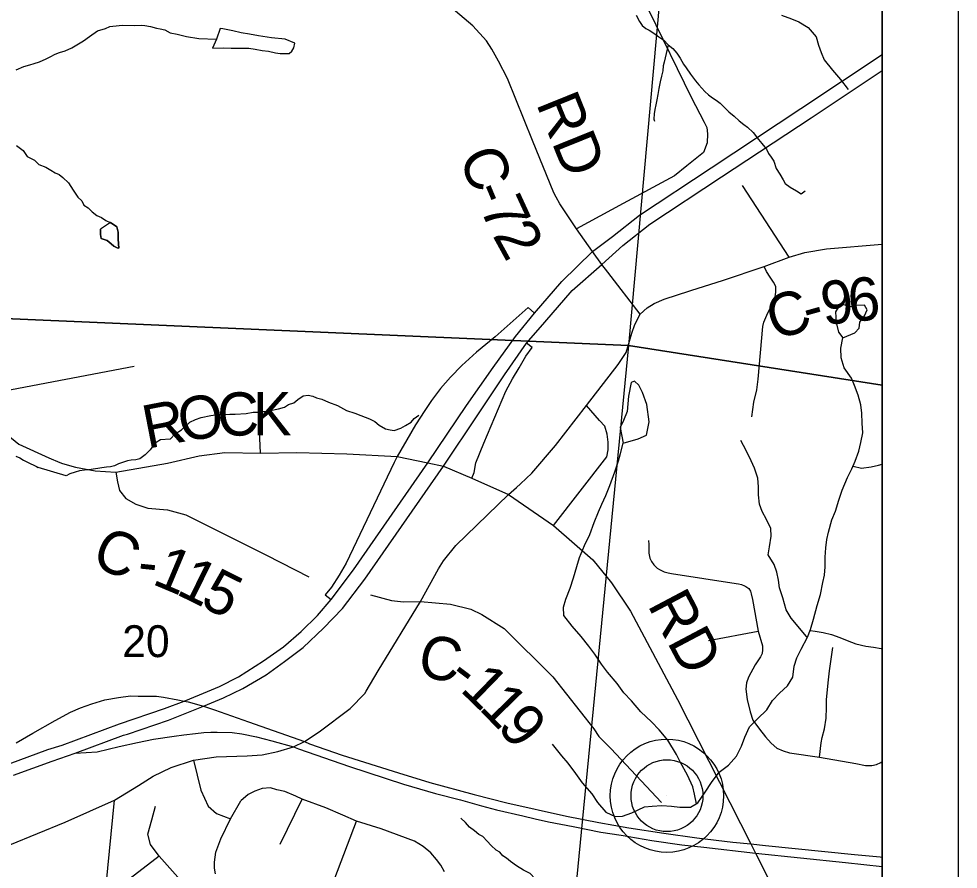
# Model space of a CAD drawing. Extents: x 0 to 34, y 0 to 22.
# Drawn here: x 7.766 to 9, y 18.274 to 19.391 of the extents above; entities that cross this region are included whole.
import ezdxf

# ---------------------------------------------------------------- set-up
doc = ezdxf.new("R2010")
doc.units = 0
for name, color, linetype in [('Default', 7, 'Continuous'), ('GM_X_County_Road', 7, 'Continuous'), ('GM_X_County_Road_Text', 7, 'Continuous'), ('GM_X_Interchange_Ramps', 7, 'Continuous'), ('GM_X_Interstate_Route', 7, 'Continuous'), ('GM_X_Minor_Lake', 7, 'Continuous'), ('GM_X_Minor_River', 7, 'Continuous'), ('GM_X_Section', 7, 'Continuous'), ('GM_X_Section_Text', 7, 'Continuous'), ('GM_X_State_Route', 7, 'Continuous'), ('GM_X_Township_Road', 7, 'Continuous'), ('GM_X_Unincorporated', 7, 'Continuous'), ('GM_X_Unincorporated_Location', 7, 'Continuous'), ('SH_Data', 7, 'Continuous')]:
    doc.layers.add(name, color=color, linetype=linetype)

msp = doc.modelspace()

# ---------------------------------------------------------------- linework, layer by layer
at = {"layer": 'Default'}
for points in [[(8.9, 18.9097), (8.9, 19.9705), (8.6611, 20.0077), (8.567, 18.9616)], [(8.9, 17.889), (8.9, 18.9097), (8.567, 18.9616), (8.4694, 17.9573)]]:
    msp.add_lwpolyline(points, close=True, dxfattribs=at)
at = {"layer": 'GM_X_County_Road'}
for p, q in [((8.778, 19.0777), (8.7165, 19.1719)), ((8.5822, 19.0027), (8.5397, 19.058))]:
    msp.add_line(p, q, dxfattribs=at)
for points in [[(8.4717, 19.1567), (8.4688, 19.1621), (8.4407, 19.2311), (8.4079, 19.3123), (8.3963, 19.335), (8.3873, 19.3508), (8.3805, 19.3619), (8.3623, 19.3818), (8.2822, 19.4501)], [(8.5937, 19.4019), (8.6494, 19.2878), (8.6662, 19.2551)], [(8.6662, 19.2551), (8.6698, 19.2481), (8.6705, 19.2395), (8.6703, 19.2278), (8.6653, 19.2154), (8.6435, 19.1977), (8.6272, 19.1847), (8.5598, 19.1481), (8.4986, 19.115)], [(8.4986, 19.115), (8.4766, 19.1477), (8.4717, 19.1567)], [(8.5397, 19.058), (8.5318, 19.0682), (8.5198, 19.085), (8.4986, 19.115)], [(8.6499, 19.0342), (8.6905, 19.0469), (8.7452, 19.0656), (8.778, 19.0777), (8.7985, 19.0836), (8.8271, 19.0886), (8.9, 19.0948)], [(8.4249, 18.7799), (8.4401, 18.7939), (8.4709, 18.8302), (8.5118, 18.8829), (8.5535, 18.9367), (8.5639, 18.9524), (8.5715, 18.9778), (8.5751, 18.9893), (8.5822, 19.0027), (8.5913, 19.0112), (8.6005, 19.017), (8.6139, 19.0226), (8.6474, 19.0334), (8.6499, 19.0342)], [(8.4686, 18.7252), (8.5386, 18.8152), (8.5403, 18.8247), (8.5404, 18.8346), (8.539, 18.8452), (8.5357, 18.8555), (8.5289, 18.8632), (8.5118, 18.8829)], [(7.7372, 18.8554), (7.7661, 18.8318), (7.8053, 18.814), (7.8201, 18.808)], [(7.8201, 18.808), (7.8236, 18.8066), (7.8405, 18.8019), (7.8662, 18.7969), (7.8933, 18.7951), (7.9615, 18.8069), (8.0028, 18.8165), (8.0365, 18.8209), (8.0835, 18.8202), (8.1311, 18.8211), (8.1969, 18.8191), (8.2631, 18.816)], [(8.2631, 18.816), (8.3033, 18.8074), (8.3237, 18.8031), (8.3611, 18.7875), (8.4094, 18.7657), (8.4686, 18.7252), (8.5201, 18.68), (8.5445, 18.6499), (8.5696, 18.6124), (8.6314, 18.4964), (8.7274, 18.307), (8.7337, 18.2945), (8.7692, 18.2244), (8.8146, 18.1608), (8.8436, 18.1295), (8.8502, 18.1228)], [(7.8933, 18.7951), (7.8955, 18.7823), (7.8985, 18.7713), (7.9068, 18.7607), (7.92, 18.7533), (7.9354, 18.7478), (7.9613, 18.7457), (7.9854, 18.739), (8.0189, 18.7224), (8.0916, 18.6863), (8.1472, 18.6575)], [(8.2224, 18.5073), (8.2383, 18.5342), (8.2936, 18.6255), (8.3174, 18.668), (8.3238, 18.6788), (8.34, 18.6988), (8.4094, 18.7657), (8.4196, 18.7751), (8.4249, 18.7799)], [(8.2279, 18.634), (8.2557, 18.6267), (8.2712, 18.625), (8.2936, 18.6255)], [(8.2936, 18.6255), (8.3333, 18.6219), (8.3596, 18.6154), (8.3742, 18.6084), (8.4035, 18.59), (8.4674, 18.5261), (8.5214, 18.4578), (8.528, 18.4479), (8.5435, 18.4322), (8.6104, 18.3614)], [(7.7625, 18.4394), (7.7846, 18.4522), (7.8139, 18.4691), (7.8341, 18.4797), (7.8472, 18.4855), (7.8618, 18.4909), (7.8791, 18.4959), (7.8971, 18.4992), (7.9126, 18.5013), (7.923, 18.501), (7.9374, 18.501), (7.9471, 18.5008), (7.9561, 18.4997), (7.975, 18.4963), (7.9833, 18.4945), (7.9887, 18.4934), (8.0087, 18.4876), (8.0231, 18.483), (8.0677, 18.467), (8.1415, 18.4413), (8.1479, 18.4383), (8.1908, 18.4236), (8.265, 18.4004), (8.3058, 18.3877), (8.3644, 18.3717), (8.4073, 18.3609), (8.4855, 18.3431), (8.5278, 18.335), (8.5673, 18.328), (8.6135, 18.321), (8.6565, 18.3149), (8.7041, 18.3091), (8.7274, 18.307), (8.7467, 18.3046), (8.8639, 18.2929), (8.8977, 18.2897), (8.9, 18.2894)], [(7.9955, 18.417), (8.0251, 18.4213), (8.0662, 18.4226), (8.0859, 18.4239), (8.1063, 18.4282), (8.1271, 18.4345), (8.1415, 18.4413), (8.1606, 18.4541), (8.2014, 18.4849), (8.2206, 18.5044), (8.2224, 18.5073)], [(7.8403, 18.426), (7.8692, 18.4277), (7.8979, 18.4348), (7.9219, 18.4399), (7.9428, 18.4443), (7.9701, 18.4483), (7.983, 18.45), (7.9983, 18.4519), (8.0093, 18.4532), (8.0182, 18.4536), (8.0267, 18.4536), (8.0462, 18.4532), (8.0591, 18.4513), (8.0784, 18.4474), (8.0985, 18.4421), (8.1271, 18.4345)], [(8.1271, 18.4345), (8.1335, 18.4316), (8.2004, 18.4087), (8.2712, 18.3853), (8.3136, 18.3729), (8.3461, 18.3645), (8.3737, 18.3567), (8.3935, 18.3517), (8.428, 18.3436), (8.4441, 18.3399), (8.462, 18.3356), (8.4943, 18.3296), (8.5305, 18.3222), (8.5574, 18.3181), (8.5975, 18.3113), (8.6369, 18.3057), (8.6657, 18.3024), (8.7337, 18.2945), (8.852, 18.2824), (8.9, 18.2773)], [(7.7543, 18.3055), (7.8269, 18.3355), (7.8918, 18.3642), (7.9232, 18.3837), (7.9426, 18.3956), (7.9661, 18.407), (7.9955, 18.417)], [(7.8771, 17.3373), (7.8654, 17.3559), (7.8589, 17.3765), (7.8552, 17.3904), (7.8533, 17.4025), (7.8533, 17.413), (7.8547, 17.4341), (7.8598, 17.4934), (7.868, 17.6036), (7.8853, 17.8757), (7.8942, 17.9932), (7.9013, 18.0969), (7.9009, 18.1021), (7.8994, 18.1068), (7.8906, 18.117), (7.8753, 18.1345), (7.8732, 18.1392), (7.8709, 18.1489), (7.8715, 18.159), (7.8918, 18.3642)]]:
    msp.add_lwpolyline(points, dxfattribs=at)
at = {"layer": 'GM_X_Interchange_Ramps'}
for points in [[(8.4433, 19.0043), (8.435, 19.0116), (8.4192, 18.9976), (8.3918, 18.9731), (8.3674, 18.9527), (8.3481, 18.9352), (8.3333, 18.9201), (8.3198, 18.9051), (8.3081, 18.8894), (8.2993, 18.8761)], [(8.3611, 18.7875), (8.3641, 18.7946), (8.3662, 18.8073), (8.3767, 18.8335), (8.4056, 18.9018), (8.4147, 18.9178), (8.4234, 18.9324), (8.4319, 18.9476), (8.4405, 18.9591), (8.433, 18.9649)], [(8.2993, 18.8761), (8.287, 18.8574), (8.2758, 18.8379), (8.2677, 18.824), (8.2631, 18.816)], [(8.2631, 18.816), (8.2589, 18.8077), (8.196, 18.6758), (8.187, 18.6601), (8.1767, 18.644), (8.1686, 18.6341), (8.1762, 18.6279)]]:
    msp.add_lwpolyline(points, dxfattribs=at)
at = {"layer": 'GM_X_Interstate_Route'}
for points in [[(7.7536, 18.4121), (7.8043, 18.4307), (7.8231, 18.4367), (7.8984, 18.4646), (7.9574, 18.4846), (7.9833, 18.4945), (8.0033, 18.5026), (8.0296, 18.5136), (8.0546, 18.5263), (8.0875, 18.5474), (8.1138, 18.5656), (8.137, 18.586), (8.1585, 18.607), (8.1762, 18.6279), (8.2056, 18.6667), (8.3033, 18.8074), (8.3542, 18.8827), (8.3893, 18.9327), (8.4183, 18.9736), (8.4433, 19.0043), (8.4794, 19.0457), (8.5198, 19.085), (8.5457, 19.1049), (8.5814, 19.1328), (8.6753, 19.195), (8.7933, 19.2729), (8.9, 19.3439)], [(7.9087, 18.4512), (7.9628, 18.4695), (8.0087, 18.4876), (8.035, 18.4986), (8.0603, 18.5112), (8.0909, 18.5291), (8.1151, 18.5466), (8.1397, 18.5649), (8.1665, 18.5902), (8.1911, 18.6159), (8.2205, 18.6546), (8.3237, 18.8031), (8.3691, 18.8706), (8.4041, 18.9231), (8.433, 18.9649), (8.457, 18.9924), (8.4931, 19.0337), (8.5318, 19.0682), (8.5594, 19.0929), (8.5951, 19.1209), (8.689, 19.1831), (8.807, 19.2609), (8.9, 19.3228)], [(7.759, 18.397), (7.8097, 18.4157), (7.8403, 18.426), (7.9038, 18.4496), (7.9087, 18.4512)]]:
    msp.add_lwpolyline(points, dxfattribs=at)
at = {"layer": 'GM_X_Minor_Lake'}
for points in [[(8.0258, 19.364), (8.0205, 19.3523), (8.035, 19.3527), (8.0448, 19.3521), (8.0547, 19.3522), (8.068, 19.3522), (8.0767, 19.3508), (8.0858, 19.3491), (8.0941, 19.3485), (8.1032, 19.346), (8.1093, 19.3454), (8.1153, 19.3453), (8.1214, 19.3451), (8.1249, 19.3484), (8.1273, 19.3529), (8.1286, 19.359), (8.1158, 19.3642), (8.098, 19.3659), (8.081, 19.3686), (8.0693, 19.3708), (8.0583, 19.3726), (8.047, 19.3752), (8.0341, 19.3778), (8.0305, 19.3783)], [(8.0305, 19.3783), (8.0258, 19.364)], [(7.8861, 19.1234), (7.8916, 19.1198), (7.895, 19.1174), (7.8967, 19.1105), (7.8964, 19.1014), (7.8973, 19.0896), (7.8954, 19.09), (7.8909, 19.092), (7.8875, 19.0952), (7.8823, 19.0995), (7.8744, 19.102), (7.8734, 19.1073), (7.8732, 19.1145)], [(7.8732, 19.1145), (7.8734, 19.1073), (7.8744, 19.102), (7.8823, 19.0995), (7.8875, 19.0952), (7.8909, 19.092), (7.8954, 19.09), (7.8973, 19.0896), (7.8964, 19.1014), (7.8967, 19.1105), (7.895, 19.1174), (7.8916, 19.1198), (7.8863, 19.1232)], [(7.8863, 19.1232), (7.8732, 19.1145)], [(8.8483, 18.9716), (8.864, 18.9782), (8.8698, 18.9842), (8.8708, 18.9921), (8.8767, 19.0004), (8.8803, 19.0086), (8.877, 19.0148), (8.8663, 19.0143), (8.8568, 19.0122), (8.8515, 19.0146), (8.8443, 19.0151), (8.8388, 19.0058), (8.8396, 18.9917)], [(8.8396, 18.9917), (8.8428, 18.9791), (8.8483, 18.9716)], [(8.5599, 18.8334), (8.5795, 18.8391), (8.5906, 18.8438), (8.594, 18.8612), (8.5911, 18.884), (8.5854, 18.8997), (8.5803, 18.9093), (8.5747, 18.9148), (8.5705, 18.913), (8.5667, 18.8952), (8.5651, 18.8751), (8.5603, 18.8631), (8.5559, 18.8537)], [(8.5559, 18.8537), (8.5599, 18.8334)]]:
    msp.add_lwpolyline(points, dxfattribs=at)
at = {"layer": 'GM_X_Minor_River'}
for points in [[(8.5769, 19.3956), (8.5812, 19.3871), (8.5849, 19.3821), (8.5897, 19.3781), (8.5942, 19.3757), (8.6002, 19.3721), (8.6069, 19.3673), (8.6132, 19.3626), (8.6192, 19.3567), (8.6251, 19.352), (8.6303, 19.3458), (8.6346, 19.3392), (8.639, 19.3314), (8.6427, 19.3264), (8.6485, 19.3182), (8.6551, 19.3093), (8.6592, 19.3042), (8.6673, 19.2952), (8.6721, 19.2909), (8.6773, 19.2869), (8.6822, 19.2838), (8.6874, 19.2798), (8.6919, 19.2755), (8.6989, 19.2688), (8.7056, 19.2629), (8.7123, 19.2566), (8.7182, 19.2519), (8.7231, 19.2483), (8.7305, 19.2413), (8.7375, 19.2323), (8.7419, 19.2272), (8.7481, 19.2195), (8.7507, 19.2137), (8.7543, 19.209), (8.7576, 19.204), (8.7608, 19.1943), (8.7659, 19.1866), (8.7699, 19.1792), (8.7728, 19.1746), (8.7791, 19.1698), (8.7877, 19.1647), (8.7937, 19.1607), (8.7991, 19.1647)], [(8.7678, 19.3958), (8.781, 19.3909), (8.7908, 19.3868), (8.8031, 19.3793), (8.8135, 19.3673), (8.8166, 19.3561), (8.8198, 19.3466), (8.8238, 19.337), (8.8348, 19.3234), (8.8455, 19.3109), (8.8555, 19.2981)], [(7.7628, 19.3237), (7.7728, 19.3283), (7.7805, 19.3303), (7.7862, 19.332), (7.7932, 19.3345), (7.802, 19.3383), (7.8074, 19.3408), (7.814, 19.3444), (7.8194, 19.3465), (7.8271, 19.3489), (7.8356, 19.3528), (7.8421, 19.3567), (7.8511, 19.3621), (7.8588, 19.3675), (7.8694, 19.3752), (7.8801, 19.3782), (7.8855, 19.3807), (7.8977, 19.3822), (7.9026, 19.3824), (7.9178, 19.3822), (7.9266, 19.3823), (7.9315, 19.3821), (7.939, 19.3807), (7.9469, 19.3785), (7.9518, 19.3776), (7.9579, 19.3763), (7.9649, 19.3726), (7.974, 19.3708), (7.9864, 19.3677), (8.0026, 19.3648), (8.0259, 19.364)], [(8.6191, 19.3567), (8.6136, 19.334), (8.6123, 19.3291), (8.6118, 19.3227), (8.6104, 19.3155), (8.6087, 19.3079), (8.6069, 19.2992), (8.6056, 19.2912), (8.6043, 19.2844), (8.6029, 19.278), (8.6013, 19.2719), (8.6007, 19.2662), (8.6001, 19.259), (8.6009, 19.2563)], [(7.7632, 19.2245), (7.772, 19.2178), (7.7771, 19.21), (7.7868, 19.2051), (7.7923, 19.1996), (7.8017, 19.1958), (7.808, 19.1918), (7.8139, 19.1886), (7.8192, 19.1865), (7.824, 19.1825), (7.8313, 19.1754), (7.8374, 19.1657), (7.8436, 19.1564), (7.8487, 19.1516), (7.8516, 19.1462), (7.8571, 19.1426), (7.8626, 19.1371), (7.8686, 19.1323), (7.8749, 19.1298), (7.8805, 19.1258), (7.8861, 19.1234)], [(8.4667, 18.4378), (8.4789, 18.4227), (8.4874, 18.413), (8.4973, 18.3994), (8.5061, 18.387), (8.5187, 18.3726), (8.526, 18.3614), (8.5371, 18.3486), (8.5495, 18.3426), (8.559, 18.3431), (8.5713, 18.3478), (8.5878, 18.3554), (8.5981, 18.3566), (8.6106, 18.3571), (8.6232, 18.3564), (8.6345, 18.355), (8.6482, 18.355), (8.6582, 18.3609), (8.6677, 18.3747), (8.676, 18.3874), (8.6858, 18.4009), (8.6982, 18.4101), (8.7087, 18.422), (8.7155, 18.4352), (8.7196, 18.4472), (8.726, 18.4608), (8.7365, 18.4712), (8.7486, 18.483), (8.7561, 18.495), (8.7651, 18.5047), (8.7756, 18.5143), (8.7827, 18.5259), (8.7846, 18.5403), (8.7879, 18.5513), (8.7939, 18.5626), (8.8019, 18.5783), (8.8059, 18.5885), (8.81, 18.6021), (8.8146, 18.6199), (8.8192, 18.6346), (8.8222, 18.6501), (8.8244, 18.6599), (8.8254, 18.6709), (8.8253, 18.6835), (8.826, 18.696), (8.8274, 18.7067), (8.8295, 18.7165), (8.8341, 18.7327), (8.8386, 18.744), (8.8431, 18.7584), (8.8476, 18.7716), (8.8545, 18.7881), (8.8604, 18.7994), (8.8645, 18.8096), (8.8694, 18.8228), (8.8719, 18.8341), (8.8749, 18.847), (8.8737, 18.8596), (8.8733, 18.8729), (8.872, 18.8836), (8.8685, 18.8962), (8.8639, 18.9089), (8.8599, 18.9185), (8.85, 18.9324), (8.8461, 18.9454), (8.8457, 18.958), (8.8483, 18.9716)], [(7.9647, 18.8386), (7.9714, 18.8456), (7.9796, 18.851), (7.9846, 18.8551), (7.9909, 18.8609), (7.9982, 18.8645), (8.0056, 18.8672), (8.0182, 18.8695), (8.0243, 18.8704), (8.0368, 18.8711), (8.0433, 18.8713), (8.0501, 18.8714), (8.0646, 18.8724), (8.0738, 18.874), (8.0813, 18.8741), (8.0871, 18.8747), (8.0947, 18.8759), (8.1073, 18.8785), (8.115, 18.8806), (8.1204, 18.8842), (8.1273, 18.8862), (8.1324, 18.8906), (8.1394, 18.8953), (8.1463, 18.8962), (8.1523, 18.8952), (8.1572, 18.8928), (8.1639, 18.891), (8.1729, 18.8873), (8.1845, 18.8827), (8.1965, 18.8762), (8.2073, 18.8728), (8.2152, 18.8695), (8.2265, 18.8653), (8.2335, 18.8616), (8.2394, 18.8569), (8.2476, 18.852), (8.2537, 18.8507), (8.2593, 18.8501), (8.2678, 18.8532), (8.274, 18.8564), (8.2813, 18.8607), (8.2853, 18.8655), (8.2915, 18.8703)], [(7.9647, 18.8386), (7.9522, 18.8379), (7.9467, 18.8343), (7.942, 18.8292), (7.9384, 18.8244), (7.9321, 18.8181), (7.9251, 18.8127), (7.9197, 18.8113), (7.9136, 18.8108), (7.9087, 18.8102), (7.9021, 18.8077), (7.8971, 18.806), (7.8917, 18.8035), (7.8864, 18.8022), (7.8814, 18.8016), (7.8753, 18.8011), (7.87, 18.8001), (7.8639, 18.7992), (7.8581, 18.7982), (7.8524, 18.7977), (7.8459, 18.7968), (7.8402, 18.7954), (7.8333, 18.793), (7.8283, 18.7905), (7.7917, 18.8015)], [(8.6561, 18.3596), (8.6536, 18.372), (8.6512, 18.382), (8.6443, 18.397), (8.6352, 18.4139), (8.6301, 18.4243), (8.6184, 18.4429), (8.607, 18.4568), (8.597, 18.4673), (8.5832, 18.4802), (8.5707, 18.4946), (8.561, 18.5051), (8.5522, 18.5175), (8.5393, 18.5326), (8.5316, 18.5431), (8.5228, 18.5559), (8.515, 18.5667), (8.5047, 18.5795), (8.4929, 18.5927), (8.4818, 18.6067), (8.4817, 18.6177), (8.4846, 18.6283), (8.4903, 18.643), (8.4948, 18.6562), (8.499, 18.6713), (8.5027, 18.683), (8.5091, 18.6988), (8.516, 18.7135), (8.5217, 18.7289), (8.5277, 18.7429), (8.5317, 18.753), (8.537, 18.7647), (8.5422, 18.7779), (8.5491, 18.7956), (8.5537, 18.8099), (8.5566, 18.8198), (8.5599, 18.8334)], [(8.8015, 18.5776), (8.8007, 18.5791), (8.7808, 18.6036), (8.7739, 18.6144), (8.7697, 18.6301), (8.7654, 18.6431), (8.7638, 18.6531), (8.7618, 18.6638), (8.7582, 18.6737), (8.7502, 18.6865), (8.7523, 18.6971), (8.7545, 18.7111), (8.7537, 18.7214), (8.7482, 18.7329), (8.7424, 18.7437), (8.7392, 18.7533), (8.7376, 18.7655), (8.7375, 18.7758), (8.7366, 18.7872), (8.7324, 18.8003), (8.7281, 18.8102), (8.7216, 18.8237), (8.7143, 18.8368)], [(7.7623, 18.8164), (7.7676, 18.8139), (7.7724, 18.8111), (7.7776, 18.8083), (7.7892, 18.8025), (7.7917, 18.8015)], [(8.8619, 18.803), (8.873, 18.8006), (8.8856, 18.8022), (8.8955, 18.8046), (8.9, 18.8059)], [(8.8054, 18.5873), (8.8119, 18.5861), (8.8225, 18.5847), (8.8335, 18.5818), (8.8444, 18.5781), (8.8542, 18.574), (8.8655, 18.5696), (8.8787, 18.5666), (8.8889, 18.5652), (8.8988, 18.5634), (8.9, 18.5633)], [(8.461, 18.2472), (8.4561, 18.25), (8.4503, 18.2567), (8.4444, 18.2611), (8.4378, 18.2681), (8.4288, 18.2723), (8.4199, 18.2779), (8.4121, 18.2835), (8.4066, 18.2882), (8.4017, 18.2911), (8.3977, 18.2961), (8.3929, 18.2986), (8.3867, 18.3049), (8.3812, 18.3104), (8.3757, 18.3167), (8.3704, 18.3191), (8.3645, 18.3239), (8.3582, 18.3287), (8.3528, 18.3349), (8.3465, 18.3405)]]:
    msp.add_lwpolyline(points, dxfattribs=at)
at = {"layer": 'GM_X_Section'}
for points in [[(7.4124, 20.0219), (8.6611, 20.0077), (8.567, 18.9616), (7.3629, 19.0139)], [(8.567, 18.9616), (8.4694, 17.9573), (7.3111, 18.02), (7.3629, 19.0139)]]:
    msp.add_lwpolyline(points, close=True, dxfattribs=at)
at = {"layer": 'GM_X_State_Route'}
msp.add_lwpolyline([(6.4637, 17.0899), (6.7527, 17.0735), (7.0496, 17.0569), (7.269, 17.0447), (7.2957, 17.0416), (7.547, 17.0195), (7.5893, 17.0158), (7.8498, 16.9928), (8.7245, 16.8871), (8.8708, 16.8659), (8.9, 16.8616), (8.9, 20.9)], dxfattribs=at)
at = {"layer": 'GM_X_Township_Road'}
for p, q in [((7.6994, 18.893), (7.9175, 18.9346)), ((8.0835, 18.8202), (8.0811, 18.8782)), ((8.6722, 18.5741), (8.7373, 18.5861)), ((8.1094, 18.3063), (8.1381, 18.3655)), ((7.9505, 18.2905), (7.9122, 18.2615))]:
    msp.add_line(p, q, dxfattribs=at)
for points in [[(8.7287, 18.8678), (8.7315, 18.887), (8.7356, 18.9034), (8.7373, 18.9175), (8.7434, 18.9864), (8.7445, 18.9922), (8.7487, 19.0016), (8.7592, 19.023), (8.7606, 19.0316), (8.7603, 19.0391), (8.7575, 19.0449), (8.7528, 19.0513), (8.7481, 19.059), (8.7452, 19.0656)], [(8.5934, 18.7055), (8.5935, 18.7001), (8.5938, 18.6889), (8.5948, 18.6822), (8.597, 18.678), (8.6004, 18.6735), (8.6047, 18.669), (8.6077, 18.6672), (8.6136, 18.6643), (8.6192, 18.6628), (8.6234, 18.662), (8.7084, 18.649), (8.7116, 18.6483), (8.7154, 18.6475), (8.7193, 18.6457), (8.7212, 18.6448), (8.7249, 18.6425), (8.7272, 18.6388), (8.7281, 18.6354), (8.7297, 18.6277), (8.7373, 18.5861), (8.7429, 18.5669), (8.7431, 18.5617), (8.7424, 18.5571), (8.7405, 18.5528), (8.7335, 18.5422), (8.7247, 18.526), (8.722, 18.5186), (8.7209, 18.51), (8.7227, 18.4967), (8.7266, 18.4804), (8.7303, 18.4695), (8.7391, 18.4575), (8.7469, 18.4475), (8.7543, 18.4391), (8.7618, 18.4327), (8.7699, 18.4289), (8.7783, 18.4263), (8.8178, 18.4207), (8.8654, 18.4124), (8.8783, 18.4098), (8.8867, 18.4097), (8.8925, 18.4112), (8.8982, 18.4136), (8.9, 18.4151)], [(8.8178, 18.4207), (8.82, 18.4395), (8.8214, 18.4465), (8.8245, 18.4582), (8.8264, 18.4719), (8.8272, 18.4861), (8.827, 18.4962), (8.8291, 18.5183), (8.8309, 18.5344), (8.8351, 18.5649)], [(7.9955, 18.417), (8.0053, 18.3776), (8.0149, 18.3564), (8.0258, 18.3466), (8.044, 18.3399)], [(8.3251, 18.2699), (8.3202, 18.2789), (8.3149, 18.2865), (8.3071, 18.2949), (8.2972, 18.3034), (8.2858, 18.3105), (8.2419, 18.3264), (8.2098, 18.3369), (8.1918, 18.3446), (8.1693, 18.3544), (8.1381, 18.3655), (8.1298, 18.3695), (8.1156, 18.3755), (8.105, 18.378), (8.0967, 18.3803), (8.0858, 18.3794), (8.0759, 18.3761), (8.0672, 18.3718), (8.0576, 18.3633)], [(8.0244, 18.2674), (8.0231, 18.275), (8.0231, 18.2827), (8.0249, 18.2959), (8.0314, 18.3133), (8.044, 18.3399), (8.0576, 18.3633)], [(8.0258, 18.2601), (8.0015, 18.2538), (7.9915, 18.2532), (7.9784, 18.2591), (7.9505, 18.2905), (7.939, 18.3062), (7.9357, 18.3194), (7.9409, 18.3383), (7.9455, 18.3564)], [(8.1641, 18.2367), (8.1748, 18.2465), (8.1811, 18.2618), (8.2098, 18.3369)]]:
    msp.add_lwpolyline(points, dxfattribs=at)
at = {"layer": 'GM_X_Unincorporated'}
for radius in [0.0744, 0.0472]:
    msp.add_circle((8.6174, 18.3701), radius, dxfattribs=at)
at = {"layer": 'GM_X_Unincorporated_Location'}
msp.add_line((8.6174, 18.3701), (8.6174, 18.3701), dxfattribs=at)
at = {"layer": 'SH_Data'}
for p, q in [((9, 21), (9, 14)), ((8.9, 20.9), (8.9, 14.1))]:
    msp.add_line(p, q, dxfattribs=at)

# ---------------------------------------------------------------- texts
at = {"layer": 'GM_X_County_Road_Text'}
for s, height, rotation, p in [('RD', 0.05682, 291.9841, (8.4451, 19.2798)), ('C', 0.0568, 292.071, (8.3433, 19.2097)), ('-', 0.0568, 292.7645, (8.3612, 19.1657)), ('7', 0.0568, 294.7204, (8.371, 19.1423)), ('2', 0.0568, 298.85, (8.3877, 19.1065)), ('6', 0.0568, 5.3418, (8.8575, 18.9924)), ('9', 0.0568, 7.3945, (8.8233, 18.988)), ('C', 0.0568, 18.36, (8.7593, 18.9677)), ('-', 0.0568, 15.5363, (8.8029, 18.9822)), ('O', 0.0568, 9.2601, (7.98, 18.8346)), ('C', 0.0568, 1.5223, (8.0274, 18.8425)), ('K', 0.0568, 0.0291, (8.0736, 18.8437)), ('R', 0.0568, 10.9718, (7.9347, 18.8258)), ('C', 0.0568, 335.5806, (7.8589, 18.6747)), ('1', 0.0568, 337.2254, (7.9396, 18.6489)), ('-', 0.0568, 354.1139, (7.9207, 18.6502)), ('1', 0.0568, 333.7654, (7.971, 18.6357)), ('5', 0.0568, 333.62, (8.0024, 18.6203)), ('RD', 0.05682, 297.897, (8.5912, 18.621)), ('C', 0.0568, 347.8331, (8.2874, 18.5287)), ('-', 0.0568, 322.8557, (8.3271, 18.5216)), ('1', 0.0568, 315.8188, (8.3443, 18.5087)), ('1', 0.0568, 314.2677, (8.3691, 18.4846)), ('9', 0.0568, 310.5275, (8.3929, 18.4602))]:
    msp.add_text(s, height=height, rotation=rotation, dxfattribs=at).set_placement(p)
at = {"layer": 'GM_X_Section_Text'}
msp.add_text('20', height=0.04186, rotation=0, dxfattribs=at).set_placement((7.9019, 18.5522))

doc.saveas('drawing.dxf')
